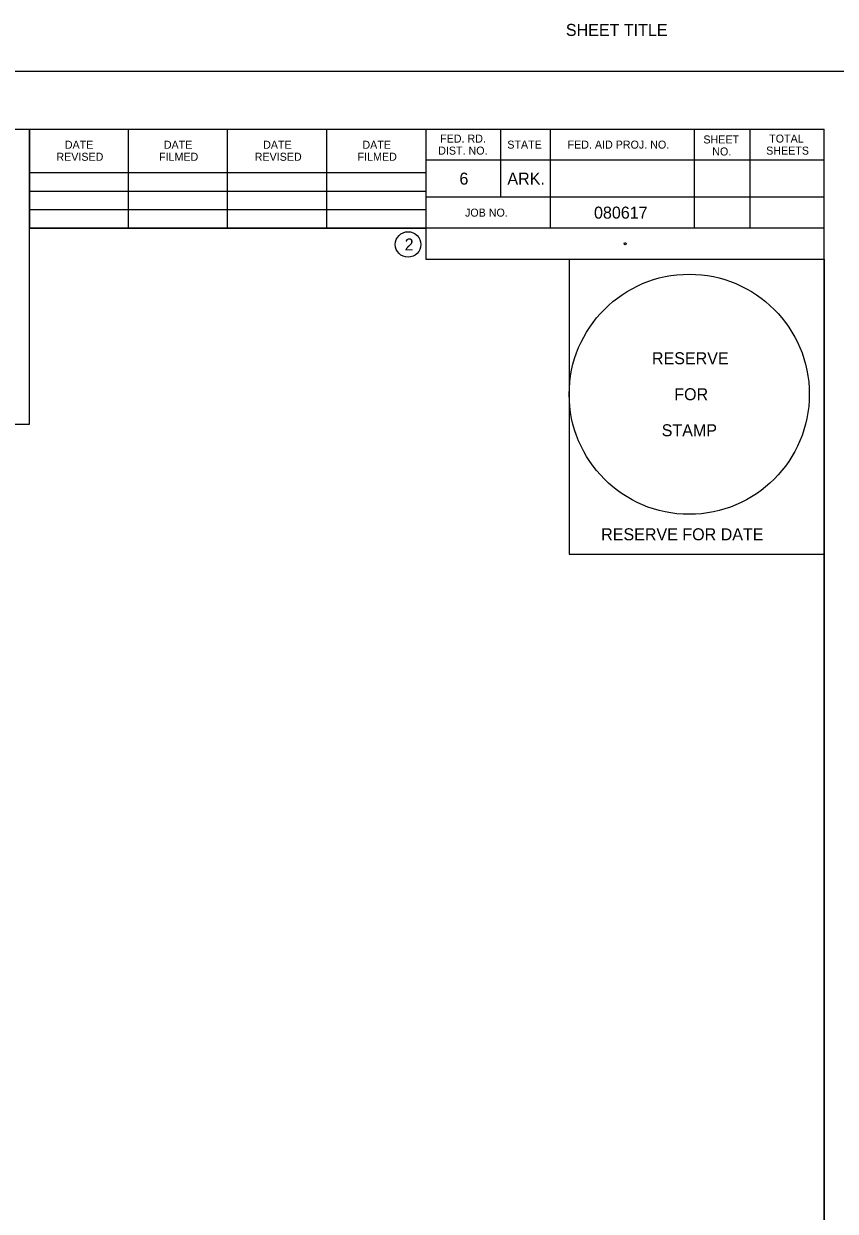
# Model space of a CAD drawing. Extents: x 0 to 19, y -0.6 to 11.2.
# Drawn here: x 12.71 to 16.77, y 5.3 to 11.24 of the extents above; entities that cross this region are included whole.
import ezdxf

# ---------------------------------------------------------------- set-up
doc = ezdxf.new("R2010")
doc.units = 0
for name, color, linetype in [('G-ANNO-TEXT', 7, 'Continuous'), ('G-Border-Paper', 7, 'Continuous'), ('G-Border-Sheet', 7, 'Continuous'), ('G-No Plot-Anchor', 7, 'Continuous'), ('G-No Plot-Border-1', 7, 'Continuous'), ('G-No Plot-Border-2', 7, 'Continuous'), ('G-No Plot-Stamp-1', 7, 'Continuous'), ('G-Table-Major', 7, 'Continuous'), ('G-Table-Minor', 7, 'Continuous')]:
    doc.layers.add(name, color=color, linetype=linetype)

msp = doc.modelspace()

# ---------------------------------------------------------------- linework, layer by layer
at = {"layer": 'G-Border-Paper'}
msp.add_lwpolyline([(17, 11), (0, 11), (0, 0), (17, 0)], close=True, dxfattribs=at)
at = {"layer": 'G-Border-Sheet'}
for p in [(0.758, 10.7116), (16.7116, 0.2884)]:
    msp.add_line(p, (16.7116, 10.7116), dxfattribs=at)
at = {"layer": 'G-No Plot-Anchor'}
msp.add_circle((15.7161, 10.1386), 0.005, dxfattribs=at)
at = {"layer": 'G-No Plot-Border-1'}
msp.add_lwpolyline([(0.758, 0.2884), (0.758, 10.7116), (12.7381, 10.7116), (12.7381, 10.2161), (14.7206, 10.2161), (14.7206, 10.0611), (15.4366, 10.0611), (15.4366, 8.5861), (16.7116, 8.5861), (16.7116, 0.2884)], close=True, dxfattribs=at)
at = {"layer": 'G-No Plot-Border-2'}
msp.add_lwpolyline([(0.758, 10.7116), (11.4739, 10.7116), (11.4739, 9.2366), (12.7381, 9.2366), (12.7381, 10.2161), (14.7206, 10.2161), (14.7206, 10.0611), (16.7116, 10.0611), (16.7116, 0.2884), (0.758, 0.2884)], close=True, dxfattribs=at)
at = {"layer": 'G-No Plot-Stamp-1'}
msp.add_circle((16.0366, 9.3861), 0.6, dxfattribs=at)
at = {"layer": 'G-Table-Major'}
for p, q in [((12.7381, 10.2161), (12.7381, 10.7116)), ((13.7281, 10.2168), (13.7281, 10.7116)), ((14.7206, 10.7116), (14.7206, 10.0611)), ((12.7381, 10.4946), (14.7206, 10.4946)), ((16.7116, 10.2161), (12.7381, 10.2161)), ((14.7206, 10.0611), (16.7116, 10.0611))]:
    msp.add_line(p, q, dxfattribs=at)
msp.add_lwpolyline([(15.2038, 10.0611), (16.7116, 10.0611), (16.7116, 8.3194)], dxfattribs=at)
msp.add_circle((14.6312, 10.1347), 0.0638, dxfattribs=at)
at = {"layer": 'G-Table-Minor'}
for p, q in [((13.2331, 10.2161), (13.2331, 10.7116)), ((14.2256, 10.2165), (14.2256, 10.7116)), ((15.0926, 10.7116), (15.0926, 10.3716)), ((15.3411, 10.7116), (15.3411, 10.2176)), ((16.0616, 10.7116), (16.0616, 10.2176)), ((16.3396, 10.7116), (16.3396, 10.2176)), ((16.7116, 10.5656), (16.7116, 10.5656)), ((16.7116, 10.5561), (14.7206, 10.5561)), ((12.7381, 10.4011), (14.7206, 10.4011)), ((16.7116, 10.3716), (14.7206, 10.3716)), ((12.7381, 10.3096), (14.7206, 10.3096))]:
    msp.add_line(p, q, dxfattribs=at)

# ---------------------------------------------------------------- texts
at = {"layer": 'G-ANNO-TEXT'}
for s, height, p in [('SHEET TITLE', 0.06, (15.4198, 11.1771)), ('TOTAL', 0.04, (16.4361, 10.6439)), ('DATE', 0.04, (12.9154, 10.6131)), ('DATE', 0.04, (13.4104, 10.6131)), ('DATE', 0.04, (13.9066, 10.6131)), ('DATE', 0.04, (14.4029, 10.6131)), ('FED. RD.', 0.04, (14.7913, 10.6439)), ('STATE', 0.04, (15.1271, 10.6139)), ('FED. AID PROJ. NO.', 0.04, (15.4283, 10.6139)), ('SHEET', 0.04, (16.1072, 10.6396)), ('REVISED', 0.04, (12.8733, 10.5531)), ('FILMED', 0.04, (13.3863, 10.5531)), ('REVISED', 0.04, (13.8646, 10.5531)), ('FILMED', 0.04, (14.3788, 10.5531)), ('DIST. NO.', 0.04, (14.7816, 10.5839)), ('NO.', 0.04, (16.1515, 10.5796)), ('SHEETS', 0.04, (16.421, 10.5839)), ('6', 0.06, (14.8879, 10.4339)), ('ARK.', 0.06, (15.1276, 10.4339)), ('JOB NO.', 0.04, (14.9156, 10.2739)), ('080617', 0.06, (15.5606, 10.2639)), ('2', 0.06, (14.6142, 10.1047))]:
    msp.add_text(s, height=height, dxfattribs=at).set_placement(p)
at = {"layer": 'G-No Plot-Stamp-1'}
for s, p in [('RESERVE', (15.85, 9.5361)), ('FOR ', (15.9617, 9.3561)), ('STAMP', (15.8989, 9.1761)), ('RESERVE FOR DATE', (15.5963, 8.6561))]:
    msp.add_text(s, height=0.06, dxfattribs=at).set_placement(p)

doc.saveas('drawing.dxf')
